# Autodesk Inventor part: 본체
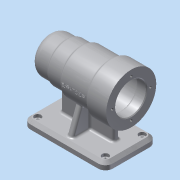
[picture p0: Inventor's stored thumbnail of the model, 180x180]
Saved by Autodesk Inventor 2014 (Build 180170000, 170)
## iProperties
Created: 2016-06
Part Number: 본체
Material: 알루미늄 6061
Document SubType Name: Modeling
Designer: SCD-A15
Density: 2.71 g/cm^3
Appearance: 알루미늄 - 평지
Mass: 672.417 g
Surface Area: 647.545 cm^2
Volume: 248.124 cm^3
Author: SCD-A15
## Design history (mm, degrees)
sketch "스케치1"
  geometry: L1 (0, 0)-(112, 0); L2 (0, 0)-(0, 25); L3 (0, 25)-(25, 25); L4 (25, 25)-(25, 27); L5 (25, 27)-(45, 27); L6 (45, 27)-(45, 30); L7 (112, 0)-(112, 34); L8 (112, 34)-(84, 34); L9 (84, 34)-(84, 30); L10 (84, 30)-(45, 30); L11 (112, 21)-(97, 21); L12 (97, 21)-(97, 24); L13 (97, 24)-(43, 24); L14 (43, 24)-(43, 21); L15 (43, 21)-(31, 21); L16 (31, 21)-(31, 17.5); L17 (31, 17.5)-(13, 17.5); L18 (13, 17.5)-(13, 16); L19 (13, 16)-(9, 16); L20 (9, 16)-(9, 10.5); L21 (9, 10.5)-(6, 10.5); L22 (6, 10.5)-(6, 0)
  constraints: 44 end point, 10 parallel, 10 perpendicular, 2 point on line, 1 collinear, 1 horizontal
  dimensions: "d0" = 50 diameter of L3 L1; "d1" = 54 diameter of L5 L1; "d2" = 60 diameter of L10 L1; "d3" = 68 diameter of L8 L1; "d4" = 112 distance of L1.start L1.end; "d5" = 84 distance between parallel lines of L2 L9; "d6" = 45 distance between parallel lines of L2 L6; "d7" = 25 distance between parallel lines of L2 L4; "d8" = 42 diameter of L11 L1; "d9" = 48 diameter of L13 L1; "d10" = 42 diameter of L15 L1; "d11" = 35 diameter of L17 L1; "d12" = 32 diameter of L19 L1; "d14" = 15 distance between parallel lines of L7 L12; "d15" = 54 distance between parallel lines of L12 L14; "d16" = 18 distance between parallel lines of L16 L18; "d17" = 12 distance between parallel lines of L14 L16; "d47" = 21 diameter of L21 L1; "d48" = 3 distance between parallel lines of L20 L22; "d49" = 4 distance between parallel lines of L18 L20
revolve "회전1" sketch "스케치1" stored, may be unused: angle "d18" = 90 deg
sketch "스케치2"
  geometry: L1 (0, -60)-(112, -60); L2 (112, -60)-(112, -70); L3 (112, -70)-(0, -70); L4 (0, -70)-(0, -60); L5 (112, -21)-(112, 21) reference; L6 (0, 0)-(112, 0); 2 further points
  constraints: 10 end point, 3 midpoint, 2 parallel, 1 horizontal, 1 perpendicular, 1 vertical alignment
  dimensions: "d19" = 70 distance between parallel lines of L3 L6; "d20" = 10 distance of L1.end L2.end; "d21" = 112 distance of L2.end L3.end
extrude "돌출1" join sketch "스케치2" stored distance "d22" = 70; taper "d23" = 0 deg
sketch "스케치3"
  geometry: L1 (0, 70)-(0, 0) reference; L2 (0, 70)-(112, 70) reference; L3 (20, 39)-(92, 39); L4 (92, 39)-(92, 31); L5 (92, 31)-(20, 31); L6 (20, 31)-(20, 39); 5 further points
  constraints: 8 end point, 4 midpoint, 2 parallel, 1 horizontal, 1 horizontal alignment, 1 perpendicular, 1 vertical alignment
  dimensions: "d24" = 20 distance between parallel lines of L6 L1; "d25" = 8 distance of L3.end L4.end
extrude "돌출2" join sketch "스케치3" stored distance "d26" = 70; taper "d27" = 0 deg
node "작업 평면1"
sketch "스케치4"
  geometry: L1 (-70, 10)-(0, 10) reference; L2 (-19.491, 44.32)-(-7, 10); L3 (-50.509, 44.32)-(-63, 10); A1 r 30 centre (-35, 70) between (-31, 40.268) and (-39, 40.268) reference; 1 further point
  constraints: 4 end point, 2 point on circle, 2 point on line
  dimensions: "d28" = 7 distance of L1.end L2.end; "d29" = 7 distance of L1.start L3.end; "d30" = 110 deg angle of L1 L2; "d31" = 110 deg angle of L1 L3
extrude "돌출3" join sketch "스케치4" stored distance "d32" = 8; taper "d33" = 0 deg
sketch "스케치5"
  geometry: C1 r 34 at (0, 0) reference; 1 further point
  constraints: 1 vertical alignment
  dimensions: "d34" = 26 distance of C1.centre point (0, 26)
hole "구멍1" sketch "스케치5" at (0, 26) diameter "d35" = 3.242; stored, may be unused: countersink angle "d39" = 90 deg, drill point angle "d41" = 118 deg; dims "d36" = 8, "d37" = 4, "d38" = 2, "d40" = 11
sketch "스케치6"
  geometry: C1 r 24 at (0, 0) reference; C2 r 24 at (0, 0)
  constraints: 1 centre point, 1 coincident, 1 concentric
extrude "돌출4" cut sketch "스케치6" distance "d45" = 8; taper "d46" = 0 deg
fillet "모깎기1" dims "d50" = 3
fillet "모깎기2" dims "d51" = 0.3
fillet "모깎기3" dims "d52" = 3
fillet "모깎기4" dims "d53" = 10
fillet "모깎기5" dims "d54" = 3
fillet "모깎기6" dims "d55" = 3
sketch "스케치7"
  geometry: L1 (52, 63)-(60, 63) reference; L2 (112, 0)-(0, 0) reference; L3 (112, 0)-(112, 70) reference; L4 (0, 70)-(112, 70) reference; L5 (9.974, 60)-(101.974, 60); L6 (101.974, 60)-(101.974, 10); L7 (101.974, 10)-(10.026, 10); 7 further points
  constraints: 6 end point, 6 midpoint, 2 parallel, 2 vertical alignment, 1 horizontal alignment, 1 perpendicular
  dimensions: "d56" = 92 distance of L5.start L5.end; "d57" = 50 distance of L5.end L6.end
hole "구멍2" sketch "스케치7" at (9.974, 60), (101.974, 60), (101.974, 10), (10.026, 10) diameter "d58" = 5; stored, may be unused: countersink angle "d62" = 90 deg, drill point angle "d64" = 118 deg; dims "d59" = 8, "d60" = 9, "d61" = 4, "d63" = 11
fillet "모깎기7" dims "d65" = 10
fillet "모깎기8" dims "d66" = 3
fillet "모깎기9" dims "d67" = 3
chamfer "모따기1" distance "d68" = 1; stored, may be unused: second distance "d69" = 2, angle "d70" = 45 deg
chamfer "모따기2" distance "d71" = 4; stored, may be unused: second distance "d72" = 2, angle "d73" = 45 deg
node "작업 평면2"
sketch "스케치8"
  geometry: L1 (112, -34)-(112, 34) reference; 2 further points
  constraints: 1 horizontal alignment, 1 other
  dimensions: "d75" = 48 distance from line of L1 point (64, 0)
feature "엠보싱1" sketch "스케치8" dims "d76" = 0.5, "d77" = 0
node "솔리드1"
pattern_circular "원형 패턴1" dims angle "d43" = 360 deg
other parameters: "d74" = 2
